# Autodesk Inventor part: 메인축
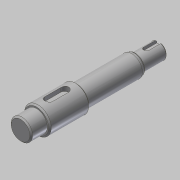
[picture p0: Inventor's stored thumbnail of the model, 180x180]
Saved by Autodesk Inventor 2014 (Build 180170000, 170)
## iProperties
Created: 2019-03
Part Number: 메인축
Material: 강철, 연강
Document SubType Name: Modeling
Designer: mduedu
Density: 1 g/cm^3
Appearance: 강철
Author: mduedu
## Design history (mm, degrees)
sketch "스케치1"
  geometry: L1 (0, 0)-(12, 0); L2 (12, 0)-(12, 8); L3 (12, 8)-(0, 8); L4 (0, 8)-(0, 0); L5 (12, 0)-(42, 0); L6 (42, 0)-(42, 10); L7 (42, 10)-(12, 10); L8 (12, 10)-(12, 0); L9 (42, 0)-(86, 0); L10 (86, 0)-(86, 8); L11 (86, 8)-(42, 8); L12 (42, 8)-(42, 0); L13 (86, 0)-(104, 0); L14 (104, 0)-(104, 6); L15 (104, 6)-(86, 6); L16 (86, 6)-(86, 0)
  constraints: 32 end point, 8 parallel, 4 horizontal, 4 perpendicular
  dimensions: "d0" = 16 diameter of L3 L1; "d2" = 20 diameter of L7 L5; "d3" = 16 diameter of L11 L9; "d4" = 12 diameter of L15 L13; "d5" = 12 distance of L2.end L3.end; "d6" = 30 distance of L6.end L7.end; "d7" = 86 distance between parallel lines of L10 L4; "d8" = 104 distance between parallel lines of L14 L4
revolve "회전1" sketch "스케치1" stored, may be unused: angle "d9" = 90 deg
node "작업 평면1"
sketch "스케치2" dims "d10" = 18
  geometry: L1 (6, -3)-(-6, -3); L2 (-6, -3)-(-6, 3); L3 (-6, 3)-(6, 3); L4 (6, 3)-(6, -3); L5 (15, 10)-(15, -10) reference; 3 further points
  constraints: 8 end point, 2 midpoint, 2 parallel, 2 vertical alignment, 1 horizontal, 1 horizontal alignment, 1 perpendicular, 4 other
  dimensions: "d12" = 6 distance between parallel lines of L3 L1; "d13" = 6 dimension on L5
extrude "돌출1" cut sketch "스케치2" distance "d14" = 3.5; taper "d15" = 0 deg
node "작업 평면2"
sketch "스케치3"
  geometry: L1 (-9, 6)-(-9, -6) reference; L2 (1, -2)-(-9, -2); L3 (1, 2)-(-9, 2); A1 r 2 centre (1, 0) between (1, -2) and (1, 2); 2 further points
  constraints: 4 end point, 2 point on circle, 2 point on line, 2 tangent, 1 centre point, 1 horizontal alignment, 1 midpoint, 1 parallel, 1 perpendicular
  dimensions: "d16" = 12 dimension on A1 L1; "d17" = 4 distance between parallel lines of L3 L2
extrude "돌출2" cut sketch "스케치3" distance "d18" = 2.5; taper "d19" = 0 deg
chamfer "모따기1" distance "d20" = 1; stored, may be unused: second distance "d21" = 2, angle "d22" = 45 deg
chamfer "모따기2" distance "d23" = 1; stored, may be unused: second distance "d24" = 2, angle "d25" = 45 deg
chamfer "모따기3" distance "d26" = 1.73; stored, may be unused: second distance "d27" = 2, angle "d28" = 30 deg
fillet "모깎기2" dims "d31" = 0.5, "d32" = 4
node "솔리드1"
